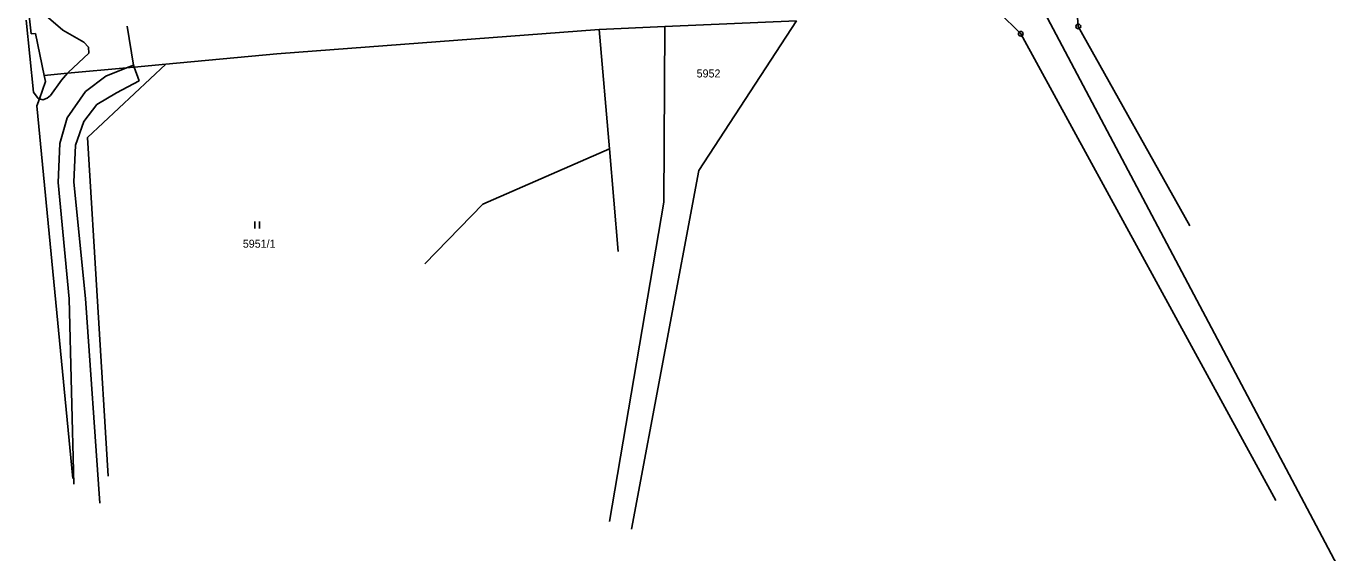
# Model space of a CAD drawing. Extents: x -735092 to -733385, y -1122435 to -1118992.
# Drawn here: x -734041 to -733762.5, y -1122225.1 to -1122113.3 of the extents above; entities that cross this region are included whole.
import ezdxf

# ---------------------------------------------------------------- set-up
doc = ezdxf.new("R2010")
doc.units = 0
for name, color, linetype in [('Vrstva 1', 7, 'Continuous'), ('Vrstva 10', 7, 'Continuous'), ('Vrstva 13', 7, 'Continuous'), ('Vrstva 18', 7, 'Continuous'), ('Vrstva 25', 7, 'Continuous'), ('Vrstva 4', 7, 'Continuous')]:
    doc.layers.add(name, color=color, linetype=linetype)

msp = doc.modelspace()

# ---------------------------------------------------------------- linework, layer by layer
at = {"layer": 'Vrstva 1'}
for points in [[(-733818.04, -1122105.5), (-733817.42, -1122113.32)], [(-734040.38, -1122110.39), (-734039.89, -1122114.9)], [(-734019.51, -1122113.24), (-734018.16, -1122121.54)], [(-733919.19, -1122113.95), (-733905.27, -1122113.34)], [(-733905.47, -1122150.65), (-733905.27, -1122113.34)], [(-733905.27, -1122113.34), (-733877.32, -1122112.11)], [(-733898.05, -1122143.91), (-733877.32, -1122112.11)], [(-733817.42, -1122113.32), (-733793.7, -1122155.64)], [(-734039.89, -1122114.9), (-734038.99, -1122114.83)], [(-734038.99, -1122114.83), (-734037.15, -1122123.72)], [(-733987.68, -1122119.15), (-733919.19, -1122113.95)], [(-733919.19, -1122113.95), (-733917.05, -1122139.33)], [(-734011.26, -1122121.33), (-733987.68, -1122119.15)], [(-734032.16, -1122123.27), (-734019.61, -1122122.11)], [(-734027.96, -1122136.92), (-734011.26, -1122121.33)], [(-734019.61, -1122122.11), (-734018, -1122121.96)], [(-734018.16, -1122121.54), (-734018, -1122121.96)], [(-734018, -1122121.96), (-734011.26, -1122121.33)], [(-734018, -1122121.96), (-734016.94, -1122124.87)], [(-734037.15, -1122123.72), (-734032.16, -1122123.27)], [(-734037.15, -1122123.72), (-734036.88, -1122125)], [(-734016.94, -1122124.87), (-734021.79, -1122127.42), (-734025.92, -1122129.9), (-734028.7, -1122133.51), (-734030.49, -1122138.57), (-734030.81, -1122146.36)], [(-734038.16, -1122128.71), (-734036.88, -1122125)], [(-734038.66, -1122130.16), (-734038.16, -1122128.71)], [(-734038.66, -1122130.16), (-734031.04, -1122209.32)], [(-734027.96, -1122136.92), (-734023.52, -1122208.83)], [(-733943.96, -1122151.07), (-733917.05, -1122139.33)], [(-733917.05, -1122139.33), (-733915.21, -1122161.15)], [(-733912.33, -1122220.12), (-733898.05, -1122143.91)], [(-734030.81, -1122146.36), (-734028.37, -1122171.11)], [(-733956.27, -1122163.78), (-733943.96, -1122151.07)], [(-733917.05, -1122218.48), (-733905.47, -1122150.65)], [(-734025.29, -1122214.61), (-734028.37, -1122171.11)]]:
    msp.add_lwpolyline(points, dxfattribs=at)
at = {"layer": 'Vrstva 10'}
msp.add_lwpolyline([(-733652.67, -1122435.07), (-733831, -1122098.21)], dxfattribs=at)
at = {"layer": 'Vrstva 13'}
for points in [[(-733834.4, -1122110.22), (-733829.65, -1122114.86)], [(-733829.65, -1122114.86), (-733775.44, -1122214.02)]]:
    msp.add_lwpolyline(points, dxfattribs=at)
at = {"layer": 'Vrstva 25'}
for points in [[(-733992.387, -1122156.225), (-733992.387, -1122154.725)], [(-733991.353, -1122156.225), (-733991.353, -1122154.725)]]:
    msp.add_lwpolyline(points, dxfattribs=at)
for centre, radius in [((-733817.42, -1122113.32), 0.5), ((-733817.42, -1122113.32), 0.032), ((-733829.65, -1122114.86), 0.5), ((-733829.65, -1122114.86), 0.032)]:
    msp.add_circle(centre, radius, dxfattribs=at)
at = {"layer": 'Vrstva 4'}
for points in [[(-734037.72, -1122110.22), (-734033.19, -1122114.12), (-734028.72, -1122116.65)], [(-734039.41, -1122127.24), (-734040.95, -1122112)], [(-734028.72, -1122116.65), (-734027.74, -1122117.7), (-734027.64, -1122118.99), (-734032.01, -1122123.1), (-734032.16, -1122123.27)], [(-734019.61, -1122122.11), (-734024.05, -1122123.86), (-734028.34, -1122127.1), (-734032.26, -1122132.74), (-734033.82, -1122138.21), (-734034.14, -1122146.47)], [(-734018.16, -1122121.54), (-734019.61, -1122122.11)], [(-734032.16, -1122123.27), (-734033.48, -1122124.74), (-734035.8, -1122127.97), (-734036.51, -1122128.58), (-734037.42, -1122128.89), (-734038.16, -1122128.71)], [(-734038.16, -1122128.71), (-734038.41, -1122128.63), (-734039.41, -1122127.24)], [(-734034.14, -1122146.47), (-734031.79, -1122171.21)], [(-734030.86, -1122210.54), (-734031.79, -1122171.21)]]:
    msp.add_lwpolyline(points, dxfattribs=at)

# ---------------------------------------------------------------- texts
at = {"layer": 'Vrstva 18'}
for s, p in [('5952', (-733898.51, -1122124.15)), ('5951/1', (-733994.93, -1122160.32))]:
    msp.add_text(s, height=1.7, dxfattribs=at).set_placement(p)

doc.saveas('drawing.dxf')
